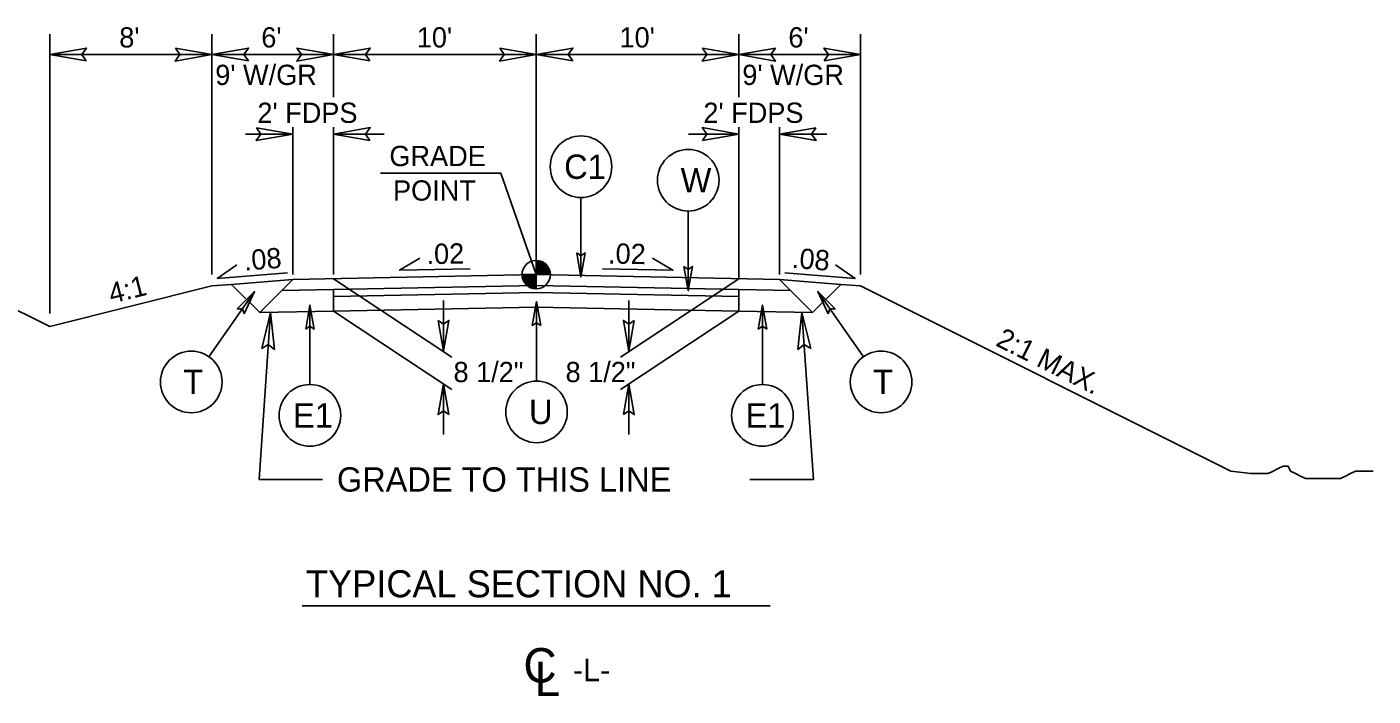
# Model space of a CAD drawing. Extents: x 574216 to 574384, y -52685 to -52551.
# Drawn here: x 574261.2 to 574327.6, y -52647.4 to -52614.4 of the extents above; entities that cross this region are included whole.
import ezdxf

# ---------------------------------------------------------------- set-up
doc = ezdxf.new("R2010")
doc.units = 0
for name, color, linetype in [('Old_Level_1', 7, 'Continuous'), ('Old_Level_15', 7, 'Continuous'), ('Old_Level_2', 7, 'Continuous'), ('Prop DSN Text', 7, 'Continuous'), ('Prop Pavement Schedule Description CELL', 7, 'Continuous'), ('Prop Terminator CELL', 7, 'Continuous')]:
    doc.layers.add(name, color=color, linetype=linetype)

msp = doc.modelspace()

# ---------------------------------------------------------------- linework, layer by layer
at = {"layer": 'Old_Level_1'}
for p, q in [((574262.322, -52628.52), (574262.322, -52614.747)), ((574270.322, -52626.601), (574270.322, -52614.747)), ((574276.322, -52617.854), (574276.322, -52614.747)), ((574286.322, -52626.601), (574286.322, -52614.747)), ((574296.322, -52617.854), (574296.322, -52614.747)), ((574302.322, -52626.601), (574302.322, -52614.747)), ((574262.322, -52615.747), (574270.322, -52615.747)), ((574270.322, -52615.747), (574276.322, -52615.747)), ((574276.322, -52615.747), (574286.322, -52615.747)), ((574286.322, -52615.747), (574296.322, -52615.747)), ((574302.322, -52615.747), (574296.322, -52615.747)), ((574274.322, -52626.601), (574274.322, -52619.333)), ((574276.322, -52626.601), (574276.322, -52619.333)), ((574296.322, -52626.801), (574296.322, -52619.333)), ((574298.322, -52626.601), (574298.322, -52619.333)), ((574271.986, -52619.67), (574274.322, -52619.67)), ((574276.322, -52619.67), (574278.815, -52619.67)), ((574296.322, -52619.67), (574293.828, -52619.67)), ((574300.657, -52619.67), (574298.322, -52619.67)), ((574262.322, -52629.161), (574252.062, -52624.031)), ((574286.322, -52626.601), (574286.322, -52625.902)), ((574286.322, -52626.601), (574274.322, -52626.841)), ((574285.622, -52626.601), (574286.322, -52626.601)), ((574286.32, -52627.301), (574286.322, -52626.601)), ((574286.322, -52626.601), (574286.32, -52627.301)), ((574287.021, -52626.601), (574286.322, -52626.601)), ((574286.322, -52626.601), (574298.322, -52626.841)), ((574270.322, -52627.161), (574262.322, -52629.161)), ((574271.297, -52627.083), (574270.322, -52627.161)), ((574274.322, -52626.841), (574271.297, -52627.083)), ((574271.297, -52627.083), (574272.689, -52628.474)), ((574274.322, -52626.841), (574272.689, -52628.474)), ((574276.322, -52627.331), (574273.781, -52627.382)), ((574276.322, -52626.801), (574282.168, -52630.669)), ((574286.318, -52627.131), (574276.322, -52627.331)), ((574276.322, -52628.402), (574276.322, -52627.331)), ((574286.326, -52627.131), (574296.322, -52627.331)), ((574296.322, -52626.801), (574290.475, -52630.669)), ((574296.322, -52628.402), (574296.322, -52627.331)), ((574296.322, -52627.331), (574298.862, -52627.382)), ((574298.322, -52626.841), (574299.954, -52628.474)), ((574298.322, -52626.841), (574301.346, -52627.083)), ((574301.346, -52627.083), (574299.954, -52628.474)), ((574301.346, -52627.083), (574302.322, -52627.161)), ((574302.322, -52627.161), (574320.581, -52636.291)), ((574286.325, -52627.481), (574276.329, -52627.681)), ((574281.751, -52630.384), (574281.751, -52627.884)), ((574286.319, -52627.481), (574296.315, -52627.681)), ((574290.892, -52630.384), (574290.892, -52627.884)), ((574276.322, -52628.402), (574272.689, -52628.474)), ((574286.318, -52628.202), (574276.322, -52628.402)), ((574276.322, -52628.402), (574282.168, -52632.269)), ((574286.326, -52628.202), (574296.322, -52628.402)), ((574296.322, -52628.402), (574290.475, -52632.269)), ((574296.322, -52628.402), (574299.954, -52628.474)), ((574281.751, -52634.484), (574281.751, -52631.984)), ((574290.892, -52634.484), (574290.892, -52631.984)), ((574274.784, -52642.936), (574297.858, -52642.936))]:
    msp.add_line(p, q, dxfattribs=at)
for points in [[(574280.586, -52625.781), (574279.584, -52626.386), (574283.06, -52626.316)], [(574286.328, -52625.902), (574286.328, -52625.902), (574286.328, -52626.601)], [(574286.342, -52625.902), (574286.342, -52626.601)], [(574286.356, -52625.903), (574286.356, -52626.601)], [(574286.37, -52625.903), (574286.37, -52626.601)], [(574286.384, -52625.905), (574286.384, -52626.601)], [(574286.398, -52625.906), (574286.398, -52626.601)], [(574286.412, -52625.908), (574286.412, -52626.601)], [(574286.426, -52625.91), (574286.426, -52626.601)], [(574286.44, -52625.911), (574286.44, -52626.601)], [(574286.454, -52625.914), (574286.454, -52626.601)], [(574286.468, -52625.917), (574286.468, -52626.601)], [(574286.482, -52625.92), (574286.482, -52626.601)], [(574286.496, -52625.924), (574286.496, -52626.601)], [(574286.51, -52625.928), (574286.51, -52626.601)], [(574286.524, -52625.931), (574286.524, -52626.601)], [(574286.538, -52625.936), (574286.538, -52626.601)], [(574286.552, -52625.941), (574286.552, -52626.601)], [(574286.566, -52625.945), (574286.566, -52626.601)], [(574286.58, -52625.952), (574286.58, -52626.601)], [(574286.594, -52625.958), (574286.594, -52626.601)], [(574286.608, -52625.964), (574286.608, -52626.601)], [(574286.622, -52625.97), (574286.622, -52626.601)], [(574286.636, -52625.976), (574286.636, -52626.601)], [(574286.649, -52625.984), (574286.649, -52626.601)], [(574286.663, -52625.992), (574286.663, -52626.601)], [(574286.677, -52626), (574286.677, -52626.601)], [(574286.691, -52626.007), (574286.691, -52626.601)], [(574286.705, -52626.017), (574286.705, -52626.601)], [(574286.719, -52626.026), (574286.719, -52626.601)], [(574286.733, -52626.037), (574286.733, -52626.601)], [(574292.06, -52625.781), (574293.063, -52626.386), (574289.587, -52626.317)], [(574271.553, -52626.125), (574270.589, -52626.789), (574274.054, -52626.512)], [(574285.625, -52626.601), (574285.625, -52626.677)], [(574285.639, -52626.601), (574285.639, -52626.76)], [(574285.653, -52626.601), (574285.653, -52626.81)], [(574285.667, -52626.601), (574285.667, -52626.852)], [(574285.681, -52626.601), (574285.681, -52626.884)], [(574285.695, -52626.601), (574285.695, -52626.914)], [(574285.709, -52626.601), (574285.709, -52626.94)], [(574285.723, -52626.601), (574285.723, -52626.965)], [(574285.737, -52626.601), (574285.737, -52626.987)], [(574285.751, -52626.601), (574285.751, -52627.007)], [(574285.765, -52626.601), (574285.765, -52627.026)], [(574285.779, -52626.601), (574285.779, -52627.043)], [(574285.793, -52626.601), (574285.793, -52627.06)], [(574285.807, -52626.601), (574285.807, -52627.075)], [(574285.821, -52626.601), (574285.821, -52627.091)], [(574285.835, -52626.601), (574285.835, -52627.105)], [(574285.849, -52626.601), (574285.849, -52627.117)], [(574285.863, -52626.601), (574285.863, -52627.13)], [(574285.877, -52626.601), (574285.877, -52627.142)], [(574285.891, -52626.601), (574285.891, -52627.153)], [(574285.905, -52626.601), (574285.905, -52627.164)], [(574285.919, -52626.601), (574285.919, -52627.173)], [(574285.933, -52626.601), (574285.933, -52627.183)], [(574285.947, -52626.601), (574285.947, -52627.192)], [(574285.961, -52626.601), (574285.961, -52627.201)], [(574285.975, -52626.601), (574285.975, -52627.209)], [(574285.989, -52626.601), (574285.989, -52627.217)], [(574286.003, -52626.601), (574286.003, -52627.225)], [(574286.017, -52626.601), (574286.017, -52627.231)], [(574286.031, -52626.601), (574286.031, -52627.237)], [(574286.045, -52626.601), (574286.045, -52627.243)], [(574286.059, -52626.601), (574286.059, -52627.249)], [(574286.073, -52626.601), (574286.073, -52627.256)], [(574286.087, -52626.601), (574286.087, -52627.26)], [(574286.101, -52626.601), (574286.101, -52627.265)], [(574286.115, -52626.601), (574286.115, -52627.27)], [(574286.129, -52626.601), (574286.129, -52627.273)], [(574286.143, -52626.601), (574286.143, -52627.277)], [(574286.157, -52626.601), (574286.157, -52627.28)], [(574286.171, -52626.601), (574286.171, -52627.284)], [(574286.185, -52626.601), (574286.185, -52627.287)], [(574286.199, -52626.601), (574286.199, -52627.29)], [(574286.213, -52626.601), (574286.213, -52627.291)], [(574286.227, -52626.601), (574286.227, -52627.294)], [(574286.241, -52626.601), (574286.241, -52627.296)], [(574286.255, -52626.601), (574286.255, -52627.298)], [(574286.269, -52626.601), (574286.269, -52627.299)], [(574286.283, -52626.601), (574286.283, -52627.299)], [(574286.297, -52626.601), (574286.297, -52627.301)], [(574286.311, -52626.601), (574286.311, -52627.301), (574286.311, -52627.301)], [(574286.747, -52626.046), (574286.747, -52626.601)], [(574286.761, -52626.057), (574286.761, -52626.601)], [(574286.775, -52626.07), (574286.775, -52626.601)], [(574286.789, -52626.082), (574286.789, -52626.601)], [(574286.803, -52626.095), (574286.803, -52626.601)], [(574286.817, -52626.109), (574286.817, -52626.601)], [(574286.831, -52626.123), (574286.831, -52626.601)], [(574286.845, -52626.138), (574286.845, -52626.601)], [(574286.859, -52626.155), (574286.859, -52626.601)], [(574286.873, -52626.172), (574286.873, -52626.601)], [(574286.887, -52626.191), (574286.887, -52626.601)], [(574286.901, -52626.211), (574286.901, -52626.601)], [(574286.915, -52626.233), (574286.915, -52626.601)], [(574286.929, -52626.256), (574286.929, -52626.601)], [(574286.943, -52626.281), (574286.943, -52626.601)], [(574286.957, -52626.311), (574286.957, -52626.601)], [(574286.971, -52626.343), (574286.971, -52626.601)], [(574286.985, -52626.382), (574286.985, -52626.601)], [(574286.999, -52626.43), (574286.999, -52626.601)], [(574287.013, -52626.502), (574287.013, -52626.601)], [(574301.09, -52626.125), (574302.054, -52626.789), (574298.589, -52626.512)], [(574320.581, -52636.291), (574321.567, -52636.414), (574321.813, -52636.414), (574322.183, -52636.414), (574322.43, -52636.414), (574322.676, -52636.291), (574322.922, -52636.168), (574323.169, -52636.044), (574323.415, -52636.044), (574323.539, -52636.291), (574323.785, -52636.414), (574324.031, -52636.538), (574324.278, -52636.66), (574324.524, -52636.66), (574324.771, -52636.66), (574325.017, -52636.66), (574325.263, -52636.66), (574325.51, -52636.66), (574325.756, -52636.66), (574326.002, -52636.66), (574326.249, -52636.538), (574326.495, -52636.414), (574326.742, -52636.291), (574327.112, -52636.291), (574327.358, -52636.291), (574327.604, -52636.291)]]:
    msp.add_lwpolyline(points, dxfattribs=at)
msp.add_circle((574286.321, -52626.601), 0.699, dxfattribs=at)
for start, end in [(359.99048, 89.99048), (179.99048, 269.99048)]:
    msp.add_arc((574286.321, -52626.601), 0.699, start, end, dxfattribs=at)
at = {"layer": 'Old_Level_15'}
for p, q in [((574278.644, -52621.599), (574284.576, -52621.599)), ((574284.576, -52621.599), (574286.322, -52626.601)), ((574272.65, -52636.713), (574273.213, -52628.464)), ((574299.993, -52636.713), (574299.43, -52628.464)), ((574275.778, -52636.713), (574272.65, -52636.713)), ((574296.865, -52636.713), (574299.993, -52636.713))]:
    msp.add_line(p, q, dxfattribs=at)
at = {"layer": 'Old_Level_2'}
for p, q in [((574288.532, -52622.797), (574288.531, -52626.722)), ((574293.82, -52623.464), (574293.82, -52627.389)), ((574270.178, -52630.65), (574272.429, -52627.435)), ((574286.339, -52631.853), (574286.339, -52627.929)), ((574302.465, -52630.65), (574300.214, -52627.435)), ((574275.16, -52632.024), (574275.159, -52628.099)), ((574297.483, -52632.024), (574297.484, -52628.099))]:
    msp.add_line(p, q, dxfattribs=at)
for points in [[(574288.323, -52625.532), (574288.532, -52625.678), (574288.74, -52625.532), (574288.531, -52626.722)], [(574293.612, -52626.199), (574293.82, -52626.345), (574294.029, -52626.199), (574293.82, -52627.389)], [(574271.918, -52628.529), (574271.83, -52628.29), (574271.576, -52628.29), (574272.429, -52627.435)], [(574286.547, -52629.118), (574286.339, -52628.972), (574286.13, -52629.118), (574286.339, -52627.929)], [(574300.725, -52628.529), (574300.813, -52628.29), (574301.067, -52628.29), (574300.214, -52627.435)], [(574274.951, -52629.289), (574275.16, -52629.143), (574275.368, -52629.289), (574275.159, -52628.099)], [(574297.692, -52629.289), (574297.483, -52629.143), (574297.275, -52629.289), (574297.484, -52628.099)]]:
    msp.add_lwpolyline(points, close=True, dxfattribs=at)
for centre in [(574288.532, -52621.278), (574293.821, -52621.945), (574269.307, -52631.894), (574303.336, -52631.894), (574286.338, -52633.372), (574275.16, -52633.543), (574297.483, -52633.543)]:
    msp.add_circle(centre, 1.519, dxfattribs=at)
at = {"layer": 'Prop DSN Text'}
for points in [[(574281.484, -52628.863), (574281.751, -52630.384), (574282.018, -52628.863), (574281.751, -52629.05)], [(574291.159, -52628.863), (574290.892, -52630.384), (574290.625, -52628.863), (574290.892, -52629.05)], [(574282.018, -52633.505), (574281.751, -52631.984), (574281.484, -52633.505), (574281.751, -52633.318)], [(574290.625, -52633.505), (574290.892, -52631.984), (574291.159, -52633.505), (574290.892, -52633.318)]]:
    msp.add_lwpolyline(points, close=True, dxfattribs=at)
at = {"layer": 'Prop Terminator CELL'}
for points in [[(574264.122, -52616.057), (574262.322, -52615.747), (574264.132, -52615.427), (574263.902, -52615.747)], [(574268.522, -52615.437), (574270.322, -52615.747), (574268.512, -52616.067), (574268.742, -52615.747)], [(574272.122, -52616.057), (574270.322, -52615.747), (574272.132, -52615.427), (574271.902, -52615.747)], [(574274.522, -52615.437), (574276.322, -52615.747), (574274.512, -52616.067), (574274.742, -52615.747)], [(574278.122, -52616.057), (574276.322, -52615.747), (574278.132, -52615.427), (574277.902, -52615.747)], [(574284.522, -52615.437), (574286.322, -52615.747), (574284.512, -52616.067), (574284.742, -52615.747)], [(574288.122, -52616.057), (574286.322, -52615.747), (574288.132, -52615.427), (574287.902, -52615.747)], [(574294.522, -52615.437), (574296.322, -52615.747), (574294.512, -52616.067), (574294.742, -52615.747)], [(574298.122, -52615.437), (574296.322, -52615.747), (574298.132, -52616.067), (574297.902, -52615.747)], [(574300.522, -52616.057), (574302.322, -52615.747), (574300.512, -52615.427), (574300.742, -52615.747)], [(574272.522, -52619.36), (574274.322, -52619.67), (574272.512, -52619.99), (574272.742, -52619.67)], [(574278.122, -52619.98), (574276.322, -52619.67), (574278.132, -52619.35), (574277.902, -52619.67)], [(574294.522, -52619.98), (574296.322, -52619.67), (574294.512, -52619.35), (574294.742, -52619.67)], [(574300.122, -52619.36), (574298.322, -52619.67), (574300.132, -52619.99), (574299.902, -52619.67)], [(574272.781, -52630.239), (574273.213, -52628.464), (574273.409, -52630.291), (574273.105, -52630.04)], [(574299.862, -52630.239), (574299.43, -52628.464), (574299.234, -52630.291), (574299.538, -52630.04)]]:
    msp.add_lwpolyline(points, close=True, dxfattribs=at)

# ---------------------------------------------------------------- texts
at = {"layer": 'Old_Level_1'}
for s, height, p in [("8'", 1, (574265.755, -52615.397)), ("6'", 1, (574272.762, -52615.397)), ("10'", 1, (574280.432, -52615.397)), ("10'", 1, (574290.432, -52615.397)), ("6'", 1, (574298.762, -52615.397)), ("9' W/GR", 1, (574270.491, -52617.247)), ("9' W/GR", 1, (574296.491, -52617.247)), ("2' FDPS", 1, (574272.57, -52619.116)), ("2' FDPS", 1, (574294.57, -52619.116)), ('GRADE', 1, (574279.081, -52621.249)), ('POINT', 1, (574279.258, -52622.949)), ('8 1/2"', 1, (574282.243, -52631.904)), ('8 1/2"', 1, (574287.77, -52631.904)), ('GRADE TO THIS LINE', 1.2, (574276.491, -52637.305)), ('TYPICAL SECTION NO. 1', 1.33333, (574274.965, -52642.517)), ('-L-', 1.1267, (574288.136, -52646.663))]:
    msp.add_text(s, height=height, dxfattribs=at).set_placement(p)
for s, rotation, p in [('.08', 4.57717, (574271.939, -52626.408)), ('.02', 1.14901, (574280.922, -52626.087)), ('.02', 358.85099, (574289.859, -52626.05)), ('.08', 355.42283, (574298.907, -52626.264)), ('4:1', 14.03624, (574265.373, -52628.038)), ('2:1 MAX.', 333.43495, (574308.939, -52630.079))]:
    msp.add_text(s, height=1, rotation=rotation, dxfattribs=at).set_placement(p)
at = {"layer": 'Old_Level_15'}
for s, p in [('C', (574285.691, -52646.72)), ('L', (574286.241, -52647.39))]:
    msp.add_text(s, height=1.698, dxfattribs=at).set_placement(p)
at = {"layer": 'Prop Pavement Schedule Description CELL'}
for s, p in [('C1', (574287.702, -52621.878)), ('W', (574293.447, -52622.545)), ('T', (574268.91, -52632.494)), ('T', (574302.94, -52632.494)), ('E1', (574274.33, -52634.143)), ('U', (574285.965, -52633.972)), ('E1', (574296.653, -52634.143))]:
    msp.add_text(s, height=1.2, dxfattribs=at).set_placement(p)

doc.saveas('drawing.dxf')
